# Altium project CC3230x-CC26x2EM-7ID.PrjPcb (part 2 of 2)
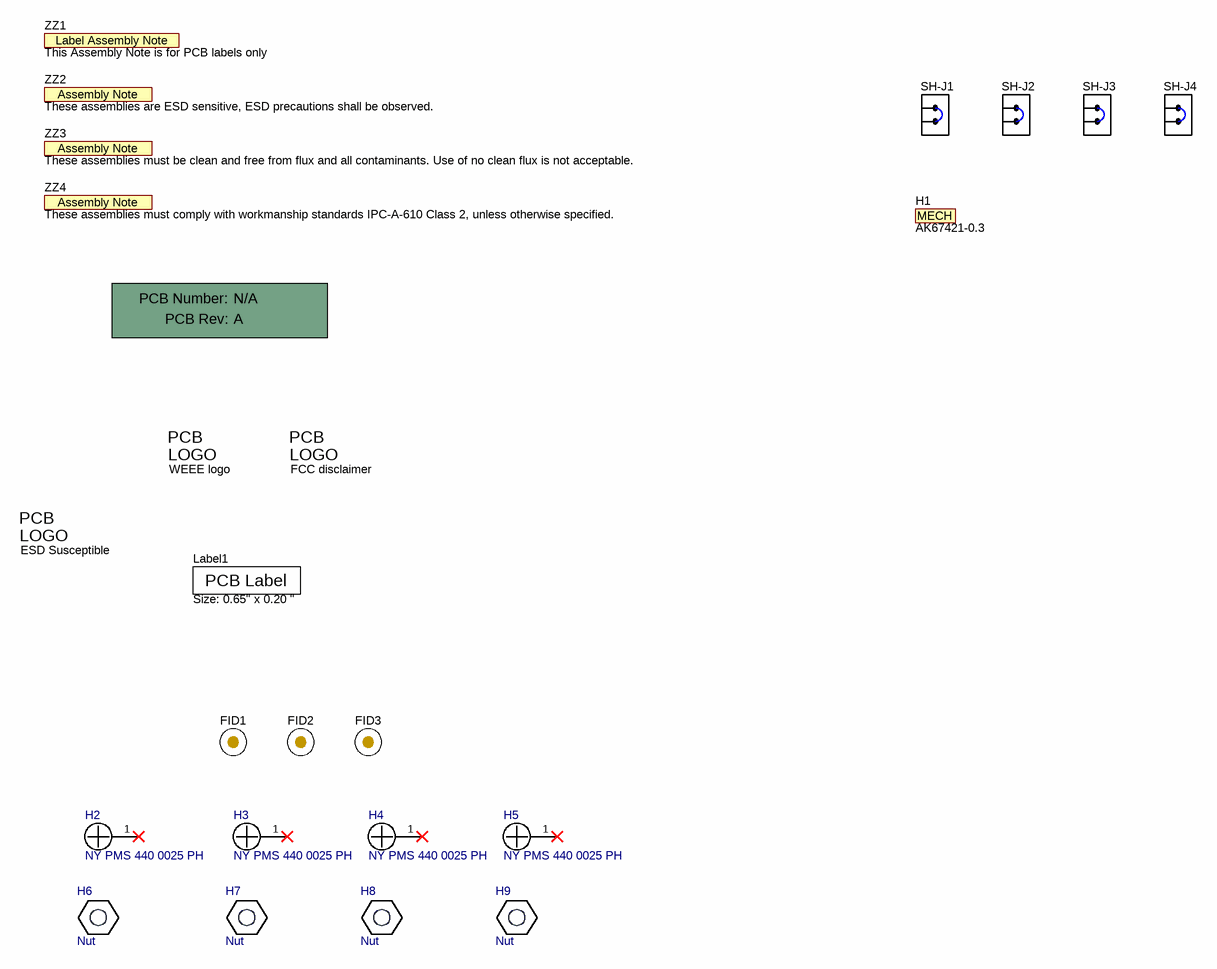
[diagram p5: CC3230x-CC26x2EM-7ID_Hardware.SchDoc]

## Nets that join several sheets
GND: CC3230x-CC26x2EM-7ID_Power_Reset_Interfaces (38 pins), CC3230x-CC26x2EM-7ID_CC3230x_EngineArea (39 pins), CC3230x-CC26x2EM-7ID_CC26x2R_EngineArea (16 pins), CC3230x-CC26x2EM-7ID_AntennaRFSection (17 pins)
VCC: CC3230x-CC26x2EM-7ID_Power_Reset_Interfaces (14 pins), CC3230x-CC26x2EM-7ID_CC3230x_EngineArea (17 pins), CC3230x-CC26x2EM-7ID_CC26x2R_EngineArea (L8.1)
VDDS: CC3230x-CC26x2EM-7ID_Power_Reset_Interfaces (R8.2), CC3230x-CC26x2EM-7ID_CC26x2R_EngineArea (10 pins)
BT_P14_DIO_8: CC3230x-CC26x2EM-7ID_Power_Reset_Interfaces (J5.2), CC3230x-CC26x2EM-7ID_CC26x2R_EngineArea (U4.14)
BT_P15_DIO_9: CC3230x-CC26x2EM-7ID_Power_Reset_Interfaces (J5.1), CC3230x-CC26x2EM-7ID_CC26x2R_EngineArea (U4.15)
BT_P19_DIO_13: CC3230x-CC26x2EM-7ID_Power_Reset_Interfaces (J7.3), CC3230x-CC26x2EM-7ID_CC26x2R_EngineArea (U4.19)
BT_P20_DIO_14: CC3230x-CC26x2EM-7ID_Power_Reset_Interfaces (J8.3), CC3230x-CC26x2EM-7ID_CC26x2R_EngineArea (U4.20)
BT_P35_nReset: CC3230x-CC26x2EM-7ID_Power_Reset_Interfaces (J2.10 J9.2), CC3230x-CC26x2EM-7ID_CC26x2R_EngineArea (U4.35)
BT_RF: CC3230x-CC26x2EM-7ID_CC26x2R_EngineArea (FL1.1), CC3230x-CC26x2EM-7ID_AntennaRFSection (R34.2)
DIO_16/JTAG_TDO: CC3230x-CC26x2EM-7ID_Power_Reset_Interfaces (J2.6), CC3230x-CC26x2EM-7ID_CC26x2R_EngineArea (U4.26)
DIO_17/JTAG_TDI: CC3230x-CC26x2EM-7ID_Power_Reset_Interfaces (J2.8), CC3230x-CC26x2EM-7ID_CC26x2R_EngineArea (U4.27)
P_24/JTAG_TMS: CC3230x-CC26x2EM-7ID_Power_Reset_Interfaces (J2.2), CC3230x-CC26x2EM-7ID_CC26x2R_EngineArea (U4.24)
P_25/JTAG_TCK: CC3230x-CC26x2EM-7ID_Power_Reset_Interfaces (J2.4), CC3230x-CC26x2EM-7ID_CC26x2R_EngineArea (U4.25)
Wi-Fi_nRESET: CC3230x-CC26x2EM-7ID_Power_Reset_Interfaces (5 pins), CC3230x-CC26x2EM-7ID_CC3230x_EngineArea (C6.1 R20.1 U3.32)
WiFi_P01_GPIO_10: CC3230x-CC26x2EM-7ID_Power_Reset_Interfaces (Q4.1 R17.1), CC3230x-CC26x2EM-7ID_CC3230x_EngineArea (U3.1)
WiFi_P02_GPIO_11: CC3230x-CC26x2EM-7ID_Power_Reset_Interfaces (Q3.1 R16.1), CC3230x-CC26x2EM-7ID_CC3230x_EngineArea (U3.2)
WiFi_P03_GPIO_12: CC3230x-CC26x2EM-7ID_CC3230x_EngineArea (U3.3), CC3230x-CC26x2EM-7ID_CC26x2R_EngineArea (U4.38)
WiFi_P04_GPIO_13: CC3230x-CC26x2EM-7ID_CC3230x_EngineArea (U3.4), CC3230x-CC26x2EM-7ID_CC26x2R_EngineArea (U4.37)
WiFi_P05_GPIO_14: CC3230x-CC26x2EM-7ID_Power_Reset_Interfaces (J7.1), CC3230x-CC26x2EM-7ID_CC3230x_EngineArea (U3.5)
WiFi_P06_GPIO_15: CC3230x-CC26x2EM-7ID_Power_Reset_Interfaces (J8.1), CC3230x-CC26x2EM-7ID_CC3230x_EngineArea (U3.6)
WiFi_P16_JTAG_TDI: CC3230x-CC26x2EM-7ID_Power_Reset_Interfaces (J1.8), CC3230x-CC26x2EM-7ID_CC3230x_EngineArea (U3.16)
WiFi_P17_JTAG_TDO: CC3230x-CC26x2EM-7ID_Power_Reset_Interfaces (J1.6), CC3230x-CC26x2EM-7ID_CC3230x_EngineArea (U3.17)
WiFi_P18_GPIO_28: CC3230x-CC26x2EM-7ID_CC3230x_EngineArea (U3.18), CC3230x-CC26x2EM-7ID_AntennaRFSection (R36.2 U5.6)
WiFi_P19_JTAG_TCK: CC3230x-CC26x2EM-7ID_Power_Reset_Interfaces (J1.4), CC3230x-CC26x2EM-7ID_CC3230x_EngineArea (U3.19)
WiFi_P20_JTAG_TMS: CC3230x-CC26x2EM-7ID_Power_Reset_Interfaces (J1.2), CC3230x-CC26x2EM-7ID_CC3230x_EngineArea (U3.20)
WiFi_P50_GPIO_00: CC3230x-CC26x2EM-7ID_CC3230x_EngineArea (U3.50), CC3230x-CC26x2EM-7ID_CC26x2R_EngineArea (U4.21)
WiFi_P53_GPIO_30: CC3230x-CC26x2EM-7ID_CC3230x_EngineArea (U3.53), CC3230x-CC26x2EM-7ID_CC26x2R_EngineArea (U4.18)
WiFi_P55_GPIO_01: CC3230x-CC26x2EM-7ID_Power_Reset_Interfaces (J6.2), CC3230x-CC26x2EM-7ID_CC3230x_EngineArea (R25.1 U3.55)
WiFi_P57_GPIO_02: CC3230x-CC26x2EM-7ID_Power_Reset_Interfaces (J6.3), CC3230x-CC26x2EM-7ID_CC3230x_EngineArea (R26.1 U3.57)
WiFi_P59_GPIO_04: CC3230x-CC26x2EM-7ID_CC3230x_EngineArea (U3.59), CC3230x-CC26x2EM-7ID_CC26x2R_EngineArea (U4.16)
WiFi_P60_GPIO_05: CC3230x-CC26x2EM-7ID_Power_Reset_Interfaces (J4.1), CC3230x-CC26x2EM-7ID_CC3230x_EngineArea (U3.60)
WiFi_P62_GPIO_07: CC3230x-CC26x2EM-7ID_Power_Reset_Interfaces (J4.2), CC3230x-CC26x2EM-7ID_CC3230x_EngineArea (U3.62)
WiFi_P63_GPIO_08: CC3230x-CC26x2EM-7ID_CC3230x_EngineArea (U3.63), CC3230x-CC26x2EM-7ID_CC26x2R_EngineArea (U4.28), CC3230x-CC26x2EM-7ID_AntennaRFSection (R35.2 U5.4)
WiFi_P64_GPIO_09: CC3230x-CC26x2EM-7ID_Power_Reset_Interfaces (Q5.1 R18.1), CC3230x-CC26x2EM-7ID_CC3230x_EngineArea (U3.64)
WIFI_RF: CC3230x-CC26x2EM-7ID_CC3230x_EngineArea (U3.31), CC3230x-CC26x2EM-7ID_AntennaRFSection (FL2.1)

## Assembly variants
CC3230SF: not fitted C9 C11 C17 C19 C32 C45 C47 C50 R27
CC3230S: not fitted C9 C11 C17 C19 C32 C45 C47 C50 L6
